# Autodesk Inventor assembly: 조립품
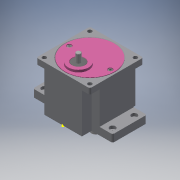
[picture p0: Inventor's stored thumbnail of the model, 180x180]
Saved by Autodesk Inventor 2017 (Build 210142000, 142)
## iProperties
Part Number: 조립품
Material: 일반
Document SubType Name: Assembly
Designer: user
Author: user
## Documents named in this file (10)
- C:\Users\user\Desktop\700116V1005\조립품.iam
- C:\Users\user\Desktop\700116V1005\메인 축.ipt
- C:\Users\user\Desktop\700116V1005\베어링 608.ipt
- C:\Users\user\Desktop\700116V1005\베어링 6003.ipt
- C:\Users\user\Desktop\700116V1005\본체.ipt
- C:\Users\user\Desktop\700116V1005\볼트 M4.ipt
- C:\Users\user\Desktop\700116V1005\서브 축.ipt
- C:\Users\user\Desktop\700116V1005\오일 실 8 22 7.ipt
- C:\Users\user\Desktop\700116V1005\오일 실 17 32 8.ipt
- C:\Users\user\Desktop\700116V1005\커버.ipt
